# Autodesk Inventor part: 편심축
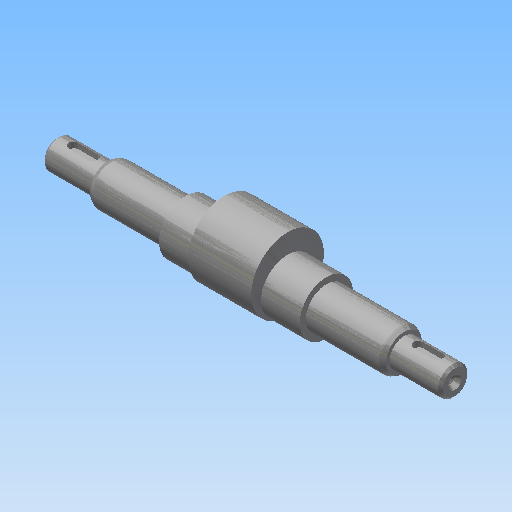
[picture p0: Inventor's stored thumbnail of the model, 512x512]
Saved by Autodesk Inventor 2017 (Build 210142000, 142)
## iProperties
Created: 2019-01
Part Number: 편심축
Material: 강철, 연강
Document SubType Name: Modeling
Designer: mduedu
Density: 7.86 g/cm^3
Appearance: 강철
Mass: 387.264 g
Surface Area: 112.62 cm^2
Volume: 49.2702 cm^3
Author: mduedu
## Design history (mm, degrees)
sketch "스케치1"
  geometry: L1 (0, 0)-(21, 0); L2 (21, 0)-(21, 6); L3 (21, 6)-(0, 6); L4 (0, 6)-(0, 0); L5 (21, 0)-(53, 0); L6 (53, 0)-(53, 8.5); L7 (53, 8.5)-(21, 8.5); L8 (21, 8.5)-(21, 0); L9 (53, 0)-(111, 0); L10 (111, 0)-(111, 11); L11 (111, 11)-(53, 11); L12 (53, 11)-(53, 0); L13 (82, 11)-(82, 0); L14 (111, 0)-(143, 0); L15 (143, 0)-(143, 8.5); L16 (143, 8.5)-(111, 8.5); L17 (111, 8.5)-(111, 0); L18 (143, 0)-(164, 0); L19 (164, 0)-(164, 6); L20 (164, 6)-(143, 6); L21 (143, 6)-(143, 0)
  constraints: 42 end point, 10 parallel, 5 horizontal, 5 perpendicular, 4 collinear, 2 midpoint
  dimensions: "d3" = 58 distance of L10.end L11.end; "d5" = 12 diameter of L3 L1; "d6" = 17 diameter of L7 L5; "d8" = 22 diameter of L11 L9; "d51" = 164 distance between parallel lines of L4 L19; "d52" = 122 distance between parallel lines of L2 L15; "d53" = 32 distance of L15.end L16.end (derived); "d54" = 32 distance of L6.end L7.end (derived)
revolve "회전1" sketch "스케치1" stored, may be unused: angle "d9" = 90 deg
node "작업 평면3"
sketch "스케치2"
  geometry: C1 r 15 at (0, 4); C2 r 11 at (0, 0); 1 further point
  constraints: 2 centre point, 1 tangent, 1 vertical alignment
  dimensions: "d11" = 4 distance of point (0, 0) C1.centre
extrude "돌출1" join sketch "스케치2" distance "d12" = 26; taper "d13" = 0 deg
node "작업 평면2"
sketch "스케치3" dims "d16" = 12
  geometry: L1 (-4.5, 2)-(3.5, 2); L2 (3.5, 2)-(3.5, -2); L3 (3.5, -2)-(-4.5, -2); L4 (-4.5, -2)-(-4.5, 2); L5 (-10.5, 8.5)-(-10.5, -8.5) reference; 3 further points
  constraints: 8 end point, 2 midpoint, 2 parallel, 2 vertical alignment, 1 horizontal, 1 horizontal alignment, 1 perpendicular, 4 other
  dimensions: "d14" = 4 distance between parallel lines of L3 L1; "d17" = 4 dimension on L5
extrude "돌출2" cut sketch "스케치3" distance "d18" = 2.5; taper "d19" = 0 deg
node "작업 평면4"
chamfer "모따기1" distance "d20" = 1.82; stored, may be unused: second distance "d21" = 2, angle "d22" = 30 deg
chamfer "모따기3" distance "d56" = 1.82; stored, may be unused: second distance "d57" = 2, angle "d58" = 30 deg
fillet "모깎기1" dims "d23" = 2
hole "구멍2" diameter "d39" = 3.242; stored, may be unused: countersink angle "d43" = 60 deg, drill point angle "d45" = 118 deg; dims "d37" = 10, "d38" = 10, "d40" = 8, "d41" = 5.51, "d42" = 2, "d44" = 10
sketch "스케치5"
  geometry: L1 (0, 0)-(2, 0); L2 (2, 0)-(2, 1.621); L3 (0, 2.776)-(0, 0); L4 (0, 2.776)-(2, 1.621); L5 (10, 1.621)-(0, 1.621) reference
  constraints: 8 end point, 1 horizontal, 1 parallel, 1 perpendicular, 1 point on line
  dimensions: "d46" = 2 distance between parallel lines of L2 L3; "d48" = 30 deg angle of L4 L1
revolve "회전2" sketch "스케치5" stored, may be unused: angle "d50" = 90 deg
chamfer "모따기2" distance "d25" = 1; stored, may be unused: second distance "d26" = 2, angle "d27" = 30 deg
node "솔리드1"
mirror "대칭1"
mirror "대칭2"
mirror "대칭3"
other parameters: "d55" = -16
